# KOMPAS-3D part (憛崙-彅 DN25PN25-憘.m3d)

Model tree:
1. Объединить компоненты:1  (labels: СЕНС-ПФ DN25PN25)
2. Эскиз:1
3. Операция выдавливания:1
     Расстояние 1 = 14
4. Фаска:1
     Угол = 45; Длина 1 = 2; Длина 2 = 2

Referenced files in D:\Савин\!СЕНСОР\3D для заказчика\!Новый перечень\СЕНС-ПФ\DN25\: СЕНС-ПФ DN25PN25.a3d
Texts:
  СЕНС-ПФ DN25PN25-СВ
  ООО НПП Сенсор
  СЕНС-ПФ DN25PN25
